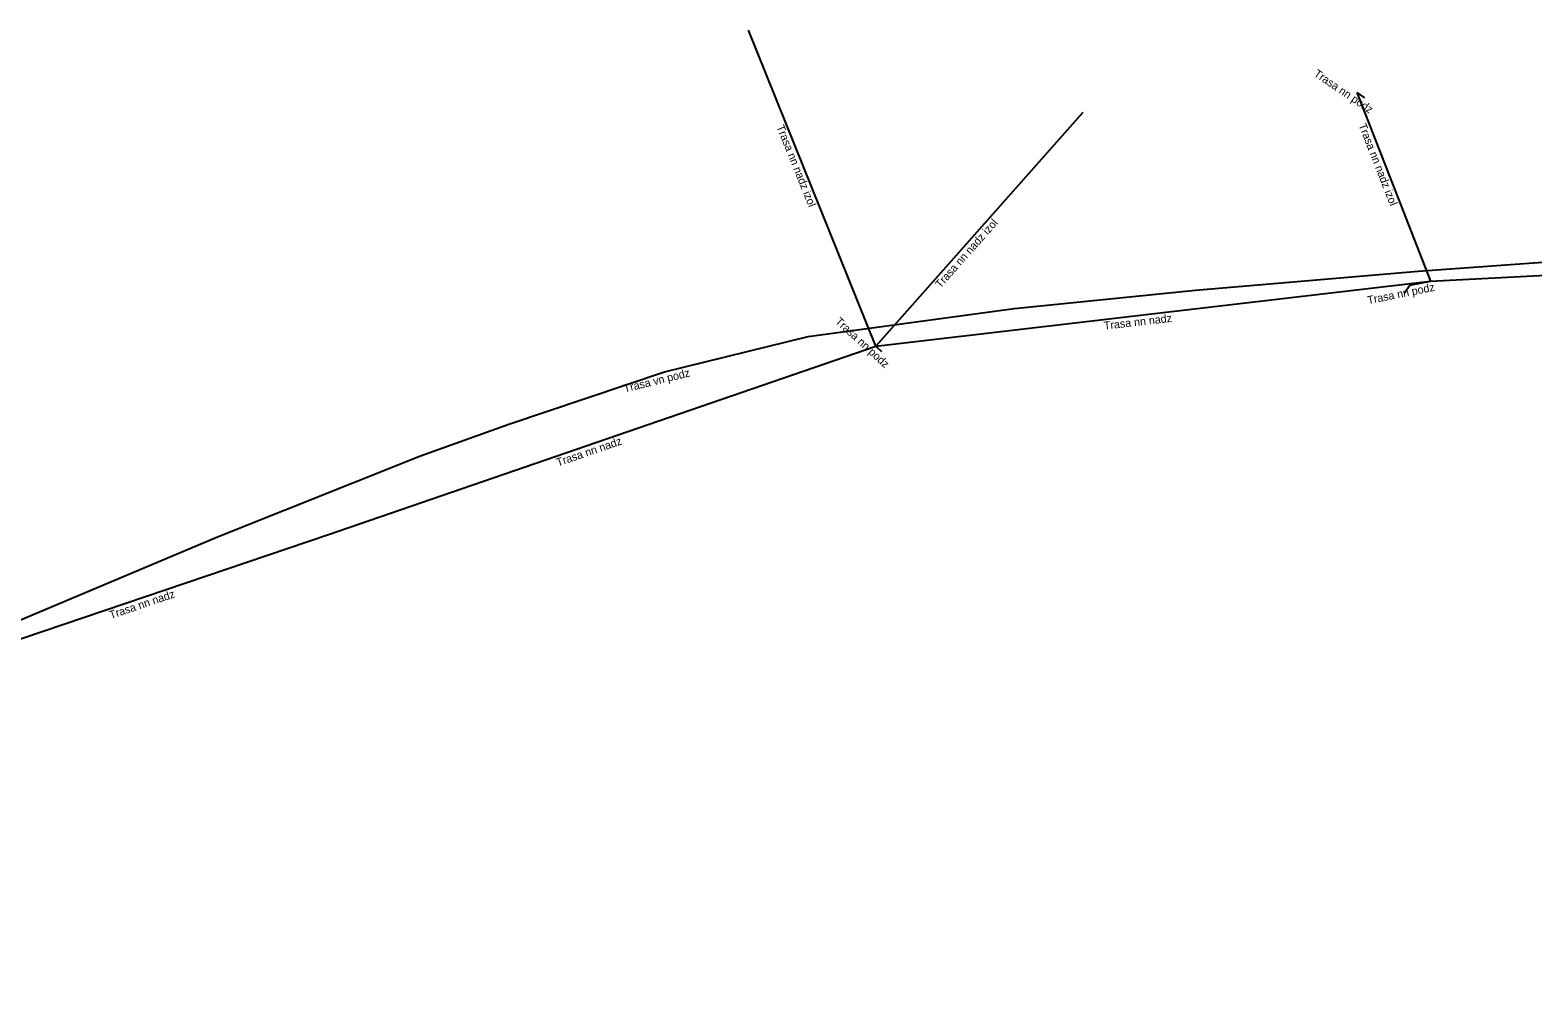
# Model space of a CAD drawing. Extents: x -682739 to -681564, y -1060091 to -1059590.
# Drawn here: x -682346.7 to -682252.8, y -1059843.2 to -1059782.9 of the extents above; entities that cross this region are included whole.
import ezdxf

# ---------------------------------------------------------------- set-up
doc = ezdxf.new("R2010")
doc.units = 0
for name, color, linetype in [('Popiskový text - Ostatní atributy Trasy', 7, 'Continuous'), ('Spojnice NN', 7, 'Continuous'), ('Spojnice VN', 7, 'Continuous')]:
    doc.layers.add(name, color=color, linetype=linetype)

msp = doc.modelspace()

# ---------------------------------------------------------------- linework, layer by layer
at = {"layer": 'Spojnice NN'}
for points in [[(-682293.87, -1059802.59), (-682301.807, -1059782.854)], [(-682263.82, -1059786.76), (-682263.348, -1059787.081)], [(-682263.82, -1059786.76), (-682259.21, -1059798.53)], [(-682280.94, -1059788), (-682293.87, -1059802.59)], [(-682259.21, -1059798.53), (-682227.92, -1059796.92)], [(-682293.87, -1059802.59), (-682259.21, -1059798.53)], [(-682260.856, -1059799.284), (-682260.502, -1059798.791), (-682259.21, -1059798.53)], [(-682328.04, -1059814.36), (-682293.87, -1059802.59)], [(-682293.87, -1059802.59), (-682293.502, -1059802.928)], [(-682349.7, -1059821.68), (-682328.04, -1059814.36)]]:
    msp.add_lwpolyline(points, dxfattribs=at)
at = {"layer": 'Spojnice VN'}
msp.add_lwpolyline([(-682419.71, -1059843.18), (-682409.04, -1059841.86), (-682401.8, -1059840.66), (-682391.43, -1059837.47), (-682378.96, -1059833.37), (-682366.87, -1059827.88), (-682350.77, -1059821.14), (-682334.98, -1059814.51), (-682322.31, -1059809.45), (-682316.78, -1059807.47), (-682307.06, -1059804.21), (-682298.09, -1059802), (-682285.23, -1059800.25), (-682273.9, -1059799.1), (-682259.98, -1059797.91), (-682246.72, -1059796.96), (-682230, -1059795.42), (-682225.98, -1059795.71), (-682224.89, -1059801.14), (-682222.94, -1059818.12), (-682221.467, -1059834.279)], dxfattribs=at)

# ---------------------------------------------------------------- texts
at = {"layer": 'Popiskový text - Ostatní atributy Trasy'}
for s, rotation, p in [('Trasa nn podz', 325.78098, (-682266.552, -1059785.688)), ('Trasa nn nadz izol', 291.90794, (-682300.08, -1059788.892)), ('Trasa nn nadz izol', 291.38897, (-682263.721, -1059788.795)), ('Trasa nn nadz izol', 48.45189, (-682289.83, -1059799.011)), ('Trasa nn podz', 11.42076, (-682263.11, -1059799.981)), ('Trasa nn podz', 317.4332, (-682296.444, -1059801.109)), ('Trasa nn nadz', 6.68106, (-682279.59, -1059801.572)), ('Trasa vn podz', 13.8407, (-682309.546, -1059805.492)), ('Trasa nn nadz', 19.00648, (-682313.72, -1059810.114)), ('Trasa nn nadz', 18.67269, (-682341.644, -1059819.644))]:
    msp.add_text(s, height=0.5, rotation=rotation, dxfattribs=at).set_placement(p)

doc.saveas('drawing.dxf')
